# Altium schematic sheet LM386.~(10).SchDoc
size A4
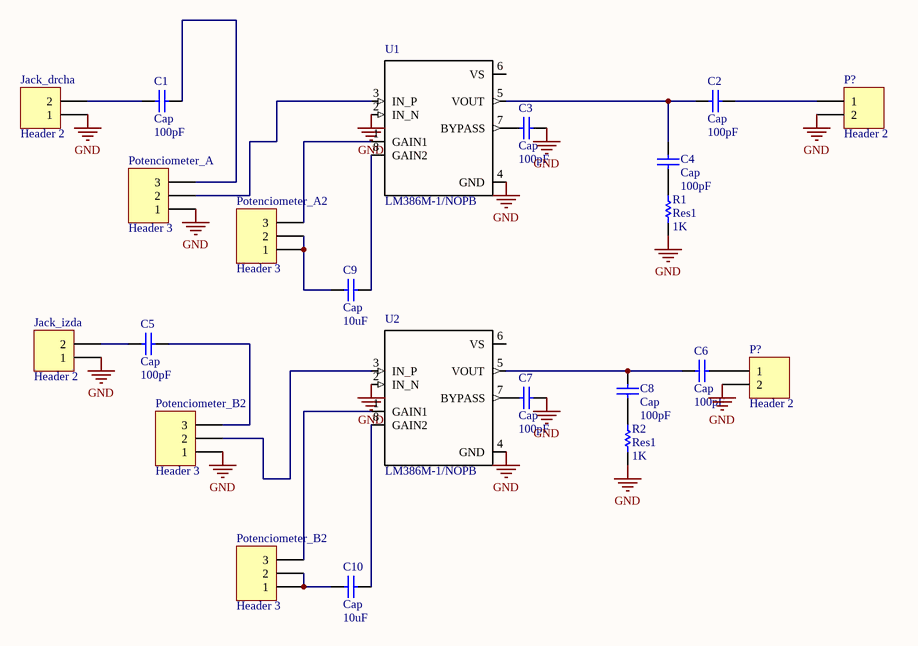
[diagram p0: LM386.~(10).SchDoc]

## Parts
(Parts that share a designator on the sheet are numbered #1, #2 ... from top to bottom, then left to right.)
C1  Cap  value 100pF  [RAD-0.3]
C2  Cap  value 100pF  [RAD-0.3]
C3  Cap  value 100pF  [RAD-0.3]
C4  Cap  value 100pF  [RAD-0.3]
C5  Cap  value 100pF  [RAD-0.3]
C6  Cap  value 100pF  [RAD-0.3]
C7  Cap  value 100pF  [RAD-0.3]
C8  Cap  value 100pF  [RAD-0.3]
C9  Cap  value 10uF  [RAD-0.3]
C10  Cap  value 10uF  [RAD-0.3]
Jack_drcha  Header 2  [HDR1X2]
Jack_izda  Header 2  [HDR1X2]
P?#1  Header 2  [HDR1X2]
P?#2  Header 2  [HDR1X2]
Potenciometer_A  Header 3  [HDR1X3]
Potenciometer_A2  Header 3  [HDR1X3]
Potenciometer_B2#1  Header 3  [HDR1X3]
Potenciometer_B2#2  Header 3  [HDR1X3]
R1  Res1  value 1K  [AXIAL-0.3]
R2  Res1  value 1K  [AXIAL-0.3]
U1  LM386M-1/NOPB  [SOIC127P600X175-8N]
U2  LM386M-1/NOPB  [SOIC127P600X175-8N]

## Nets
GND: C3.1 C7.2 Jack_drcha.1 Jack_izda.1 P?#1.2 P?#2.2 Potenciometer_A.1 Potenciometer_B2#1.1 R1.1 R2.1 U1.2(IN_N) U1.4(GND) U2.2(IN_N) U2.4(GND)
NetC1_1: C1.1 Potenciometer_A.3
NetC1_2: C1.2 Jack_drcha.2
NetC2_1: C2.1 C4.2 U1.5(VOUT)
NetC2_2: C2.2 P?#1.1
NetC3_2: C3.2 U1.7(BYPASS)
NetC4_1: C4.1 R1.2
NetC5_1: C5.1 Potenciometer_B2#1.3
NetC5_2: C5.2 Jack_izda.2
NetC6_1: C6.1 C8.2 U2.5(VOUT)
NetC6_2: C6.2 P?#2.1
NetC7_1: C7.1 U2.7(BYPASS)
NetC8_1: C8.1 R2.2
NetC9_1: C9.1 U1.8(GAIN2)
NetC9_2: C9.2 Potenciometer_A2.1 Potenciometer_A2.2
NetC10_1: C10.1 U2.8(GAIN2)
NetC10_2: C10.2 Potenciometer_B2#2.1 Potenciometer_B2#2.2
NetPotenciometer_A2_3: Potenciometer_A2.3 U1.1(GAIN1)
NetPotenciometer_A_2: Potenciometer_A.2 U1.3(IN_P)
NetPotenciometer_B2#1_2: Potenciometer_B2#1.2 U2.3(IN_P)
NetPotenciometer_B2#2_3: Potenciometer_B2#2.3 U2.1(GAIN1)

Not connected (* = marked no-connect by the designer): U1 6(VS); U2 6(VS)

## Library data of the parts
C1-C10 = Cap: Capacitor
Jack_drcha Jack_izda P?#1 P?#2 = Header 2: Header, 2-Pin
Potenciometer_A Potenciometer_A2 Potenciometer_B2#1 Potenciometer_B2#2 = Header 3: Header, 3-Pin
R1 R2 = Res1: Resistor
U1 U2 = LM386M-1/NOPB: Wide Input Voltage Low Power Audio Amplifier with Internal Gain 8-SOIC 0 to 70; MF: Texas Instruments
